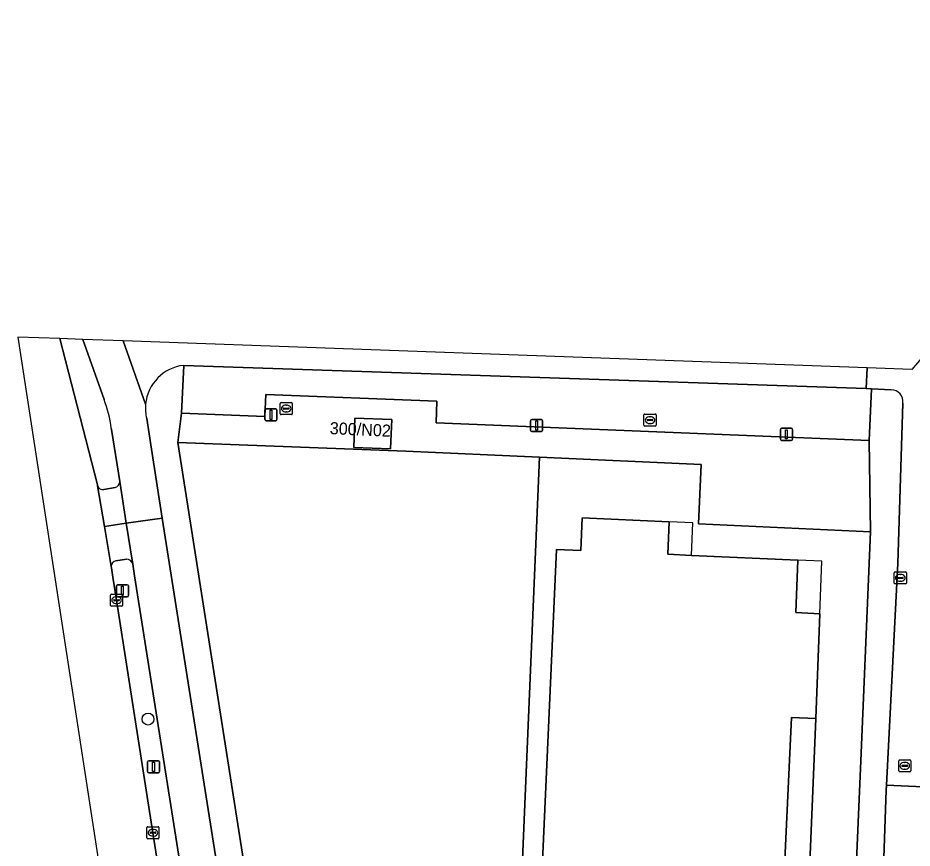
# Model space of a CAD drawing. Extents: x 160888 to 161385, y 386490 to 386908.
# Drawn here: x 160887.8 to 160961.8, y 386837.1 to 386905.8 of the extents above; entities that cross this region are included whole.
import ezdxf

# ---------------------------------------------------------------- set-up
doc = ezdxf.new("R2010")
doc.units = 0
for name, color, linetype in [('IMGEO_Berm_groen', 7, 'Continuous'), ('IMGEO_Boom', 7, 'Continuous'), ('IMGEO_Brandkraan', 7, 'Continuous'), ('IMGEO_Erf', 7, 'Continuous'), ('IMGEO_Fietspad_gesloten', 7, 'Continuous'), ('IMGEO_Fietspad_open', 7, 'Continuous'), ('IMGEO_Groenvoorziening', 7, 'Continuous'), ('IMGEO_Kolk', 7, 'Continuous'), ('IMGEO_Lichtmast', 7, 'Continuous'), ('IMGEO_Pand', 7, 'Continuous'), ('IMGEO_Pand_nummerreeks', 7, 'Continuous'), ('IMGEO_Pand_overbouw', 7, 'Continuous'), ('IMGEO_Rijbaan_lokaal_gesloten', 7, 'Continuous'), ('IMGEO_Rijbaan_lokaal_open', 7, 'Continuous'), ('IMGEO_Rioolput', 7, 'Continuous'), ('IMGEO_Verkeersbordpaal', 7, 'Continuous'), ('IMGEO_Verkeerseiland_groen', 7, 'Continuous'), ('IMGEO_Voetpad_open', 7, 'Continuous')]:
    doc.layers.add(name, color=color, linetype=linetype)

msp = doc.modelspace()

# ---------------------------------------------------------------- linework, layer by layer
at = {"layer": 'IMGEO_Berm_groen'}
for points in [[(160896.751, 386860.973), (160895.883, 386860.825)], [(160895.489, 386860.369), (160895.508, 386860.258), (160895.636, 386859.48), (160895.937, 386857.577), (160898.944, 386838.332), (160902.899, 386813.113), (160906.087, 386792.878), (160909.252, 386772.655), (160912.737, 386750.44), (160912.804, 386750), (160913.758, 386743.775)], [(160904.689, 386813.559), (160897.429, 386859.589), (160897.273, 386860.565)]]:
    msp.add_lwpolyline(points, dxfattribs=at)
for centre, radius, start, end in [((160895.931, 386860.385), 0.442, 96.23838, 182.10529), ((160896.786, 386860.48), 0.494, 9.92501, 94.05197)]:
    msp.add_arc(centre, radius, start, end, dxfattribs=at)
at = {"layer": 'IMGEO_Boom'}
msp.add_circle((160898.541, 386847.738), 0.489, dxfattribs=at)
at = {"layer": 'IMGEO_Brandkraan'}
for p, q in [((160960.654, 386843.444), (160960.654, 386844.296)), ((160960.729, 386844.37), (160961.581, 386844.37)), ((160960.913, 386843.864), (160960.913, 386843.876)), ((160961.351, 386843.827), (160960.953, 386843.827)), ((160960.956, 386843.913), (160961.354, 386843.913)), ((160961.142, 386844.15), (160961.167, 386844.15)), ((160961.397, 386843.876), (160961.397, 386843.864)), ((160961.655, 386844.296), (160961.655, 386843.444)), ((160961.581, 386843.37), (160960.729, 386843.37)), ((160961.165, 386843.59), (160961.14, 386843.59))]:
    msp.add_line(p, q, dxfattribs=at)
for points in [[(160960.654, 386843.444), (160960.654, 386844.296)], [(160960.729, 386844.37), (160961.581, 386844.37)], [(160961.655, 386844.296), (160961.655, 386843.444)], [(160961.581, 386843.37), (160960.729, 386843.37)]]:
    msp.add_lwpolyline(points, dxfattribs=at)
for centre, radius, start, end in [((160960.731, 386844.294), 0.0765, 91.55205, 178.44795), ((160960.731, 386844.294), 0.0765, 91.55205, 178.44795), ((160960.953, 386843.873), 0.0403, 85.87752, 175.75265), ((160960.95, 386843.863), 0.0366, 178.93798, 274.71019), ((160961.354, 386843.87), 0.043, 264.86636, 352.45326), ((160961.358, 386843.875), 0.0386, 1.73085, 96.63898), ((160961.579, 386844.294), 0.0765, 1.55205, 88.44795), ((160961.579, 386844.294), 0.0765, 1.55205, 88.44795), ((160960.731, 386843.446), 0.0765, 181.55205, 268.44795), ((160960.731, 386843.446), 0.0765, 181.55205, 268.44795), ((160961.579, 386843.446), 0.0765, 271.55205, 358.44795), ((160961.579, 386843.446), 0.0765, 271.55205, 358.44795)]:
    msp.add_arc(centre, radius, start, end, dxfattribs=at)
for centre, major_axis, ratio, start_param, end_param in [((160961.141, 386843.87), (-0.387, 0.002), 0.722429, 4.712389, 7.853982), ((160961.166, 386843.87), (-0.39, 0.002), 0.717154, 1.570796, 4.712389)]:
    msp.add_ellipse(centre, major_axis=major_axis, ratio=ratio, start_param=start_param, end_param=end_param, dxfattribs=at)
at = {"layer": 'IMGEO_Erf'}
msp.add_lwpolyline([(160953.788, 386847.794), (160951.78, 386847.873), (160949.448, 386797.758), (160951.446, 386797.676), (160950.315, 386763.859), (160952.108, 386763.787), (160953.498, 386797.543), (160954.852, 386797.5), (160955.314, 386809.236), (160952.198, 386809.36)], close=True, dxfattribs=at)
at = {"layer": 'IMGEO_Fietspad_gesloten'}
for points in [[(160896.482, 386879.04), (160893.132, 386879.162), (160894.9, 386874.198)], [(160898.337, 386873.806), (160896.482, 386879.04)], [(160958.056, 386876.81), (160896.482, 386879.04), (160898.337, 386873.806)], [(160901.489, 386877.014), (160957.962, 386875.093), (160958.056, 386876.81)], [(160895.497, 386871.813), (160895.518, 386871.708), (160896.217, 386867.408), (160896.734, 386863.953), (160899.722, 386864.375), (160898.823, 386870.088), (160898.426, 386872.614)], [(160894.371, 386867.052), (160894.934, 386863.689), (160896.734, 386863.953), (160896.217, 386867.408)], [(160895.81, 386866.893), (160894.883, 386866.73)], [(160907.589, 386814.399), (160899.722, 386864.375), (160896.734, 386863.953), (160897.273, 386860.565), (160897.429, 386859.589), (160904.689, 386813.559)]]:
    msp.add_lwpolyline(points, dxfattribs=at)
for centre, radius, start, end in [((160901.888, 386873.47), 3.567, 96.42224, 174.58672), ((160885.253, 386870.516), 10.325, 7.21566, 20.89074), ((160901.872, 386873.471), 3.551, 174.5804, 193.95967), ((160895.601, 386867.477), 0.62, 289.71072, 353.65126), ((160894.793, 386867.155), 0.434, 193.70288, 281.96504)]:
    msp.add_arc(centre, radius, start, end, dxfattribs=at)
at = {"layer": 'IMGEO_Fietspad_open'}
for points in [[(160989.598, 386903.645), (160988.842, 386904.061), (160987.414, 386904.997), (160986.431, 386905.776), (160986.431, 386905.776), (160961.742, 386876.676), (160958.056, 386876.81)], [(160958.056, 386876.81), (160957.962, 386875.093), (160958.414, 386875.075), (160960.041, 386874.995)], [(160960.986, 386873.9), (160960.591, 386860.622), (160959.632, 386842.271), (160962.072, 386842.148), (160963.58, 386842.073)]]:
    msp.add_lwpolyline(points, dxfattribs=at)
msp.add_arc((160960.047, 386874.045), 0.95, 351.22726, 90.36203, dxfattribs=at)
at = {"layer": 'IMGEO_Groenvoorziening'}
msp.add_lwpolyline([(160957.962, 386875.093), (160901.489, 386877.014), (160901.306, 386873.07), (160908.206, 386872.785), (160908.279, 386874.602), (160922.446, 386874.058), (160922.377, 386872.253), (160958.216, 386870.789), (160958.414, 386875.075)], close=True, dxfattribs=at)
for points in [[(160930.929, 386869.413), (160919.86, 386869.902), (160901.002, 386870.642), (160909.808, 386814.589), (160919.923, 386750), (160920.871, 386743.948)], [(160921.858, 386743.044), (160929.897, 386742.707), (160930.028, 386750), (160930.114, 386754.806), (160929.938, 386754.813), (160929.987, 386755.938), (160928.176, 386756.029), (160929.806, 386796.624), (160929.436, 386796.639), (160929.5, 386798.18), (160927.927, 386798.235), (160930.929, 386869.413)]]:
    msp.add_lwpolyline(points, dxfattribs=at)
at = {"layer": 'IMGEO_Kolk'}
for p, q in [((160960.287, 386859.002), (160960.287, 386859.854)), ((160960.362, 386859.928), (160961.214, 386859.928)), ((160960.546, 386859.422), (160960.546, 386859.434)), ((160960.984, 386859.385), (160960.586, 386859.385)), ((160960.589, 386859.471), (160960.987, 386859.471)), ((160960.775, 386859.708), (160960.8, 386859.708)), ((160961.03, 386859.434), (160961.03, 386859.422)), ((160961.288, 386859.854), (160961.288, 386859.002)), ((160961.214, 386858.928), (160960.362, 386858.928)), ((160960.798, 386859.148), (160960.773, 386859.148)), ((160895.436, 386857.151), (160895.436, 386858.003)), ((160895.511, 386858.077), (160896.363, 386858.077)), ((160895.924, 386857.857), (160895.949, 386857.857)), ((160896.437, 386858.003), (160896.437, 386857.151)), ((160896.363, 386857.077), (160895.511, 386857.077)), ((160895.695, 386857.571), (160895.695, 386857.583)), ((160896.133, 386857.534), (160895.735, 386857.534)), ((160895.738, 386857.62), (160896.136, 386857.62)), ((160895.947, 386857.297), (160895.922, 386857.297)), ((160896.179, 386857.583), (160896.179, 386857.571)), ((160898.443, 386837.906), (160898.443, 386838.758)), ((160898.518, 386838.832), (160899.37, 386838.832)), ((160898.931, 386838.612), (160898.956, 386838.612)), ((160899.444, 386838.758), (160899.444, 386837.906)), ((160899.37, 386837.832), (160898.518, 386837.832)), ((160898.702, 386838.326), (160898.702, 386838.338)), ((160899.14, 386838.289), (160898.742, 386838.289)), ((160898.745, 386838.375), (160899.143, 386838.375)), ((160898.954, 386838.052), (160898.929, 386838.052)), ((160899.186, 386838.338), (160899.186, 386838.326))]:
    msp.add_line(p, q, dxfattribs=at)
for points in [[(160960.287, 386859.002), (160960.287, 386859.854)], [(160960.362, 386859.928), (160961.214, 386859.928)], [(160961.288, 386859.854), (160961.288, 386859.002)], [(160961.214, 386858.928), (160960.362, 386858.928)], [(160895.436, 386857.151), (160895.436, 386858.003)], [(160895.511, 386858.077), (160896.363, 386858.077)], [(160896.437, 386858.003), (160896.437, 386857.151)], [(160896.363, 386857.077), (160895.511, 386857.077)], [(160898.443, 386837.906), (160898.443, 386838.758)], [(160898.518, 386838.832), (160899.37, 386838.832)], [(160899.444, 386838.758), (160899.444, 386837.906)], [(160899.37, 386837.832), (160898.518, 386837.832)]]:
    msp.add_lwpolyline(points, dxfattribs=at)
for centre, radius, start, end in [((160960.364, 386859.852), 0.0765, 91.55205, 178.44795), ((160960.364, 386859.852), 0.0765, 91.55205, 178.44795), ((160960.586, 386859.431), 0.0403, 85.87752, 175.75265), ((160960.583, 386859.421), 0.0366, 178.93798, 274.71019), ((160960.987, 386859.428), 0.043, 264.86636, 352.45326), ((160960.991, 386859.433), 0.0386, 1.73085, 96.63898), ((160961.212, 386859.852), 0.0765, 1.55205, 88.44795), ((160961.212, 386859.852), 0.0765, 1.55205, 88.44795), ((160960.364, 386859.004), 0.0765, 181.55205, 268.44795), ((160960.364, 386859.004), 0.0765, 181.55205, 268.44795), ((160961.212, 386859.004), 0.0765, 271.55205, 358.44795), ((160961.212, 386859.004), 0.0765, 271.55205, 358.44795), ((160895.513, 386858.001), 0.0765, 91.55205, 178.44795), ((160895.513, 386858.001), 0.0765, 91.55205, 178.44795), ((160896.361, 386858.001), 0.0765, 1.55205, 88.44795), ((160896.361, 386858.001), 0.0765, 1.55205, 88.44795), ((160895.513, 386857.153), 0.0765, 181.55205, 268.44795), ((160895.513, 386857.153), 0.0765, 181.55205, 268.44795), ((160895.735, 386857.58), 0.0403, 85.87752, 175.75265), ((160895.732, 386857.57), 0.0366, 178.93798, 274.71019), ((160896.136, 386857.577), 0.043, 264.86636, 352.45326), ((160896.14, 386857.582), 0.0386, 1.73085, 96.63898), ((160896.361, 386857.153), 0.0765, 271.55205, 358.44795), ((160896.361, 386857.153), 0.0765, 271.55205, 358.44795), ((160898.52, 386838.756), 0.0765, 91.55205, 178.44795), ((160898.52, 386838.756), 0.0765, 91.55205, 178.44795), ((160899.368, 386838.756), 0.0765, 1.55205, 88.44795), ((160899.368, 386838.756), 0.0765, 1.55205, 88.44795), ((160898.52, 386837.908), 0.0765, 181.55205, 268.44795), ((160898.52, 386837.908), 0.0765, 181.55205, 268.44795), ((160898.742, 386838.335), 0.0403, 85.87752, 175.75265), ((160898.739, 386838.325), 0.0366, 178.93798, 274.71019), ((160899.143, 386838.332), 0.043, 264.86636, 352.45326), ((160899.147, 386838.337), 0.0386, 1.73085, 96.63898), ((160899.368, 386837.908), 0.0765, 271.55205, 358.44795), ((160899.368, 386837.908), 0.0765, 271.55205, 358.44795)]:
    msp.add_arc(centre, radius, start, end, dxfattribs=at)
for centre, major_axis, ratio, start_param, end_param in [((160960.774, 386859.428), (-0.387, 0.002), 0.722429, 4.712389, 7.853982), ((160960.799, 386859.428), (-0.39, 0.002), 0.717154, 1.570796, 4.712389), ((160895.923, 386857.577), (-0.387, 0.002), 0.722429, 4.712389, 7.853982), ((160895.948, 386857.577), (-0.39, 0.002), 0.717154, 1.570796, 4.712389), ((160898.93, 386838.332), (-0.387, 0.002), 0.722429, 4.712389, 7.853982), ((160898.955, 386838.332), (-0.39, 0.002), 0.717154, 1.570796, 4.712389)]:
    msp.add_ellipse(centre, major_axis=major_axis, ratio=ratio, start_param=start_param, end_param=end_param, dxfattribs=at)
at = {"layer": 'IMGEO_Lichtmast'}
for p, q in [((160908.216, 386872.523), (160908.216, 386873.323)), ((160908.216, 386873.323), (160908.216, 386872.523)), ((160908.316, 386873.423), (160909.106, 386873.423)), ((160909.106, 386873.423), (160908.316, 386873.423)), ((160909.206, 386873.323), (160909.206, 386872.523)), ((160909.206, 386872.523), (160909.206, 386873.323)), ((160909.106, 386872.423), (160908.316, 386872.423)), ((160908.316, 386872.423), (160909.106, 386872.423)), ((160930.197, 386871.637), (160930.197, 386872.437)), ((160930.197, 386872.437), (160930.197, 386871.637)), ((160930.297, 386872.537), (160931.087, 386872.537)), ((160931.087, 386872.537), (160930.297, 386872.537)), ((160931.187, 386872.437), (160931.187, 386871.637)), ((160931.187, 386871.637), (160931.187, 386872.437)), ((160931.087, 386871.537), (160930.297, 386871.537)), ((160930.297, 386871.537), (160931.087, 386871.537)), ((160950.863, 386870.906), (160950.863, 386871.706)), ((160950.863, 386871.706), (160950.863, 386870.906)), ((160950.963, 386871.806), (160951.753, 386871.806)), ((160951.753, 386871.806), (160950.963, 386871.806)), ((160951.853, 386871.706), (160951.853, 386870.906)), ((160951.853, 386870.906), (160951.853, 386871.706)), ((160951.753, 386870.806), (160950.963, 386870.806)), ((160950.963, 386870.806), (160951.753, 386870.806)), ((160895.922, 386857.964), (160895.922, 386858.764)), ((160895.922, 386858.764), (160895.922, 386857.964)), ((160896.022, 386858.864), (160896.812, 386858.864)), ((160896.812, 386858.864), (160896.022, 386858.864)), ((160896.912, 386858.764), (160896.912, 386857.964)), ((160896.912, 386857.964), (160896.912, 386858.764)), ((160896.812, 386857.864), (160896.022, 386857.864)), ((160896.022, 386857.864), (160896.812, 386857.864))]:
    msp.add_line(p, q, dxfattribs=at)
for points in [[(160908.636, 386873.298), (160908.786, 386873.298), (160908.786, 386872.548), (160908.636, 386872.548), (160908.636, 386873.298)], [(160930.617, 386872.412), (160930.767, 386872.412), (160930.767, 386871.662), (160930.617, 386871.662), (160930.617, 386872.412)], [(160951.283, 386871.681), (160951.433, 386871.681), (160951.433, 386870.931), (160951.283, 386870.931), (160951.283, 386871.681)], [(160896.342, 386858.739), (160896.492, 386858.739), (160896.492, 386857.989), (160896.342, 386857.989), (160896.342, 386858.739)]]:
    msp.add_lwpolyline(points, dxfattribs=at)
for centre, start, end in [((160908.316, 386873.323), 90, 180), ((160908.316, 386873.323), 90, 180), ((160909.106, 386873.323), 0, 90), ((160909.106, 386873.323), 360, 90), ((160908.316, 386872.523), 180, 270), ((160908.316, 386872.523), 180, 270), ((160909.106, 386872.523), 270, 0), ((160909.106, 386872.523), 270, 0), ((160930.297, 386872.437), 90, 180), ((160930.297, 386872.437), 90, 180), ((160931.087, 386872.437), 0, 90), ((160931.087, 386872.437), 360, 90), ((160930.297, 386871.637), 180, 270), ((160930.297, 386871.637), 180, 270), ((160931.087, 386871.637), 270, 0), ((160931.087, 386871.637), 270, 0), ((160950.963, 386871.706), 90, 180), ((160950.963, 386871.706), 90, 180), ((160951.753, 386871.706), 0, 90), ((160951.753, 386871.706), 360, 90), ((160950.963, 386870.906), 180, 270), ((160950.963, 386870.906), 180, 270), ((160951.753, 386870.906), 270, 0), ((160951.753, 386870.906), 270, 0), ((160896.022, 386858.764), 90, 180), ((160896.022, 386858.764), 90, 180), ((160896.812, 386858.764), 0, 90), ((160896.812, 386858.764), 360, 90), ((160896.022, 386857.964), 180, 270), ((160896.022, 386857.964), 180, 270), ((160896.812, 386857.964), 270, 0), ((160896.812, 386857.964), 270, 0)]:
    msp.add_arc(centre, 0.1, start, end, dxfattribs=at)
at = {"layer": 'IMGEO_Pand'}
msp.add_lwpolyline([(160918.707, 386872.537), (160915.658, 386872.659), (160915.56, 386870.217), (160918.609, 386870.095)], close=True, dxfattribs=at)
msp.add_lwpolyline([(160949.448, 386797.758), (160951.78, 386847.873), (160953.788, 386847.794), (160954.129, 386856.46), (160952.148, 386856.549), (160952.319, 386860.893), (160943.509, 386861.288), (160941.548, 386861.376), (160941.654, 386864.075), (160934.451, 386864.398), (160934.345, 386861.699), (160932.347, 386861.777), (160929.668, 386802.21)], dxfattribs=at)
at = {"layer": 'IMGEO_Pand_overbouw'}
for points in [[(160941.654, 386864.075), (160941.548, 386861.376), (160943.509, 386861.288), (160943.619, 386863.992)], [(160954.129, 386856.46), (160954.283, 386860.798), (160952.319, 386860.893), (160952.148, 386856.549)], [(160953.788, 386847.794), (160951.78, 386847.873), (160949.448, 386797.758), (160951.446, 386797.676), (160950.315, 386763.859), (160952.108, 386763.787), (160953.498, 386797.543), (160953.65, 386801.238), (160953.658, 386801.438), (160953.82, 386805.388), (160953.828, 386805.588), (160952.045, 386805.661), (160952.198, 386809.36)]]:
    msp.add_lwpolyline(points, close=True, dxfattribs=at)
at = {"layer": 'IMGEO_Rijbaan_lokaal_gesloten'}
for points in [[(160887.77, 386879.356), (160914.501, 386705.629)], [(160918.036, 386737.106), (160917.275, 386737.753), (160916.574, 386738.465), (160915.94, 386739.237), (160915.378, 386740.062), (160914.891, 386740.934), (160914.487, 386741.731), (160914.076, 386742.739), (160913.758, 386743.775), (160912.804, 386750), (160912.737, 386750.44), (160909.252, 386772.655), (160906.087, 386792.878), (160902.899, 386813.113), (160898.944, 386838.332), (160895.937, 386857.577), (160895.636, 386859.48), (160895.508, 386860.258), (160895.489, 386860.369), (160894.934, 386863.689), (160894.371, 386867.052), (160894.361, 386867.114), (160891.251, 386879.23), (160887.77, 386879.356)]]:
    msp.add_lwpolyline(points, dxfattribs=at)
at = {"layer": 'IMGEO_Rijbaan_lokaal_open'}
msp.add_lwpolyline([(161043.522, 386832.446), (161043.806, 386838.784), (161039.187, 386838.995), (161037.473, 386839.083), (161032.49, 386839.326), (161030.999, 386839.386), (161012.875, 386840.109), (160995.572, 386840.8), (160970.959, 386841.804), (160969.349, 386841.87), (160964.719, 386842.033), (160963.58, 386842.073), (160962.072, 386842.148), (160959.632, 386842.271), (160959.61, 386841.85), (160959.238, 386830.691)], dxfattribs=at)
at = {"layer": 'IMGEO_Rioolput'}
for p, q in [((160909.474, 386873.012), (160909.474, 386873.864)), ((160909.549, 386873.938), (160910.401, 386873.938)), ((160909.733, 386873.432), (160909.733, 386873.444)), ((160910.171, 386873.395), (160909.773, 386873.395)), ((160909.776, 386873.481), (160910.174, 386873.481)), ((160909.962, 386873.718), (160909.987, 386873.718)), ((160910.217, 386873.444), (160910.217, 386873.432)), ((160910.475, 386873.864), (160910.475, 386873.012)), ((160910.401, 386872.938), (160909.549, 386872.938)), ((160909.985, 386873.158), (160909.96, 386873.158)), ((160939.576, 386872.061), (160939.576, 386872.913)), ((160939.651, 386872.987), (160940.503, 386872.987)), ((160940.064, 386872.767), (160940.089, 386872.767)), ((160940.577, 386872.913), (160940.577, 386872.061)), ((160940.503, 386871.987), (160939.651, 386871.987)), ((160939.835, 386872.481), (160939.835, 386872.493)), ((160940.273, 386872.444), (160939.875, 386872.444)), ((160939.878, 386872.53), (160940.276, 386872.53)), ((160940.087, 386872.207), (160940.062, 386872.207)), ((160940.319, 386872.493), (160940.319, 386872.481))]:
    msp.add_line(p, q, dxfattribs=at)
for points in [[(160909.474, 386873.012), (160909.474, 386873.864)], [(160909.549, 386873.938), (160910.401, 386873.938)], [(160910.475, 386873.864), (160910.475, 386873.012)], [(160910.401, 386872.938), (160909.549, 386872.938)], [(160939.576, 386872.061), (160939.576, 386872.913)], [(160939.651, 386872.987), (160940.503, 386872.987)], [(160940.577, 386872.913), (160940.577, 386872.061)], [(160940.503, 386871.987), (160939.651, 386871.987)]]:
    msp.add_lwpolyline(points, dxfattribs=at)
for centre, radius, start, end in [((160909.551, 386873.862), 0.0765, 91.55205, 178.44795), ((160909.551, 386873.862), 0.0765, 91.55205, 178.44795), ((160909.773, 386873.441), 0.0403, 85.87752, 175.75265), ((160909.77, 386873.431), 0.0366, 178.93798, 274.71019), ((160910.174, 386873.438), 0.043, 264.86636, 352.45326), ((160910.178, 386873.443), 0.0386, 1.73085, 96.63898), ((160910.399, 386873.862), 0.0765, 1.55205, 88.44795), ((160910.399, 386873.862), 0.0765, 1.55205, 88.44795), ((160909.551, 386873.014), 0.0765, 181.55205, 268.44795), ((160909.551, 386873.014), 0.0765, 181.55205, 268.44795), ((160910.399, 386873.014), 0.0765, 271.55205, 358.44795), ((160910.399, 386873.014), 0.0765, 271.55205, 358.44795), ((160939.653, 386872.911), 0.0765, 91.55205, 178.44795), ((160939.653, 386872.911), 0.0765, 91.55205, 178.44795), ((160940.501, 386872.911), 0.0765, 1.55205, 88.44795), ((160940.501, 386872.911), 0.0765, 1.55205, 88.44795), ((160939.653, 386872.063), 0.0765, 181.55205, 268.44795), ((160939.653, 386872.063), 0.0765, 181.55205, 268.44795), ((160939.875, 386872.49), 0.0403, 85.87752, 175.75265), ((160939.872, 386872.48), 0.0366, 178.93798, 274.71019), ((160940.276, 386872.487), 0.043, 264.86636, 352.45326), ((160940.28, 386872.492), 0.0386, 1.73085, 96.63898), ((160940.501, 386872.063), 0.0765, 271.55205, 358.44795), ((160940.501, 386872.063), 0.0765, 271.55205, 358.44795)]:
    msp.add_arc(centre, radius, start, end, dxfattribs=at)
for centre, major_axis, ratio, start_param, end_param in [((160909.961, 386873.438), (-0.387, 0.002), 0.722429, 4.712389, 7.853982), ((160909.986, 386873.438), (-0.39, 0.002), 0.717154, 1.570796, 4.712389), ((160940.063, 386872.487), (-0.387, 0.002), 0.722429, 4.712389, 7.853982), ((160940.088, 386872.487), (-0.39, 0.002), 0.717154, 1.570796, 4.712389)]:
    msp.add_ellipse(centre, major_axis=major_axis, ratio=ratio, start_param=start_param, end_param=end_param, dxfattribs=at)
at = {"layer": 'IMGEO_Verkeersbordpaal'}
for p, q in [((160898.502, 386843.387), (160898.502, 386844.187)), ((160898.502, 386844.187), (160898.502, 386843.387)), ((160898.602, 386844.287), (160899.392, 386844.287)), ((160899.392, 386844.287), (160898.602, 386844.287)), ((160899.492, 386844.187), (160899.492, 386843.387)), ((160899.492, 386843.387), (160899.492, 386844.187)), ((160899.392, 386843.287), (160898.602, 386843.287)), ((160898.602, 386843.287), (160899.392, 386843.287))]:
    msp.add_line(p, q, dxfattribs=at)
msp.add_lwpolyline([(160898.922, 386844.162), (160899.072, 386844.162), (160899.072, 386843.412), (160898.922, 386843.412), (160898.922, 386844.162)], dxfattribs=at)
for centre, start, end in [((160898.602, 386844.187), 90, 180), ((160898.602, 386844.187), 90, 180), ((160899.392, 386844.187), 0, 90), ((160899.392, 386844.187), 360, 90), ((160898.602, 386843.387), 180, 270), ((160898.602, 386843.387), 180, 270), ((160899.392, 386843.387), 270, 0), ((160899.392, 386843.387), 270, 0)]:
    msp.add_arc(centre, 0.1, start, end, dxfattribs=at)
at = {"layer": 'IMGEO_Verkeerseiland_groen'}
for points in [[(160893.132, 386879.162), (160891.251, 386879.23), (160894.361, 386867.114), (160894.371, 386867.052)], [(160894.9, 386874.198), (160893.132, 386879.162)], [(160896.217, 386867.408), (160895.518, 386871.708), (160895.497, 386871.813)], [(160894.883, 386866.73), (160895.81, 386866.893)]]:
    msp.add_lwpolyline(points, dxfattribs=at)
for centre, radius, start, end in [((160885.253, 386870.516), 10.325, 7.21566, 20.89074), ((160895.601, 386867.477), 0.62, 289.71072, 353.65126), ((160894.793, 386867.155), 0.434, 193.70288, 281.96504)]:
    msp.add_arc(centre, radius, start, end, dxfattribs=at)
at = {"layer": 'IMGEO_Voetpad_open'}
for points in [[(160909.808, 386814.589), (160901.002, 386870.642), (160901.306, 386873.07), (160901.489, 386877.014)], [(160960.041, 386874.995), (160958.414, 386875.075), (160958.216, 386870.789), (160958.321, 386863.241), (160957.528, 386844.274), (160956.638, 386823.929)], [(160957.867, 386796.743), (160957.427, 386796.742), (160957.557, 386800.529), (160958.012, 386800.522), (160958.394, 386810.023), (160957.96, 386810.032), (160958.098, 386813.821), (160958.543, 386813.81), (160959.074, 386826.917), (160958.637, 386826.939), (160958.774, 386830.722), (160959.238, 386830.691), (160959.61, 386841.85), (160959.632, 386842.271), (160960.591, 386860.622), (160960.986, 386873.9)], [(160898.426, 386872.614), (160898.823, 386870.088), (160899.722, 386864.375), (160907.589, 386814.399), (160917.197, 386753.124), (160917.572, 386751.136), (160917.807, 386750), (160919.245, 386743.063), (160921.858, 386743.044)], [(160956.638, 386823.929), (160957.528, 386844.274), (160958.321, 386863.241), (160944.088, 386863.91), (160944.3, 386868.823), (160930.929, 386869.413), (160927.927, 386798.235)], [(160896.734, 386863.953), (160894.934, 386863.689), (160895.489, 386860.369)], [(160897.273, 386860.565), (160896.734, 386863.953)], [(160929.668, 386802.21), (160932.347, 386861.777), (160934.345, 386861.699), (160934.451, 386864.398), (160941.654, 386864.075), (160941.548, 386861.376), (160943.509, 386861.288), (160952.319, 386860.893), (160952.148, 386856.549), (160954.129, 386856.46), (160953.788, 386847.794), (160952.198, 386809.36)], [(160895.883, 386860.825), (160896.751, 386860.973)]]:
    msp.add_lwpolyline(points, dxfattribs=at)
for points in [[(160958.216, 386870.789), (160922.377, 386872.253), (160922.446, 386874.058), (160908.279, 386874.602), (160908.206, 386872.785), (160901.306, 386873.07), (160901.002, 386870.642), (160919.86, 386869.902), (160930.929, 386869.413), (160944.3, 386868.823), (160944.088, 386863.91), (160958.321, 386863.241)], [(160918.609, 386870.095), (160915.56, 386870.217), (160915.658, 386872.659), (160918.707, 386872.537)]]:
    msp.add_lwpolyline(points, close=True, dxfattribs=at)
for centre, radius, start, end in [((160901.888, 386873.47), 3.567, 96.42224, 174.58672), ((160960.047, 386874.045), 0.95, 351.22726, 90.36203), ((160901.872, 386873.471), 3.551, 174.5804, 193.95967), ((160895.931, 386860.385), 0.442, 96.23838, 182.10529), ((160896.786, 386860.48), 0.494, 9.92501, 94.05197)]:
    msp.add_arc(centre, radius, start, end, dxfattribs=at)

# ---------------------------------------------------------------- texts
at = {"layer": 'IMGEO_Pand_nummerreeks'}
msp.add_text('300/N02', height=1, rotation=357.42308, dxfattribs=at).set_placement((160913.558, 386871.328))

doc.saveas('drawing.dxf')
